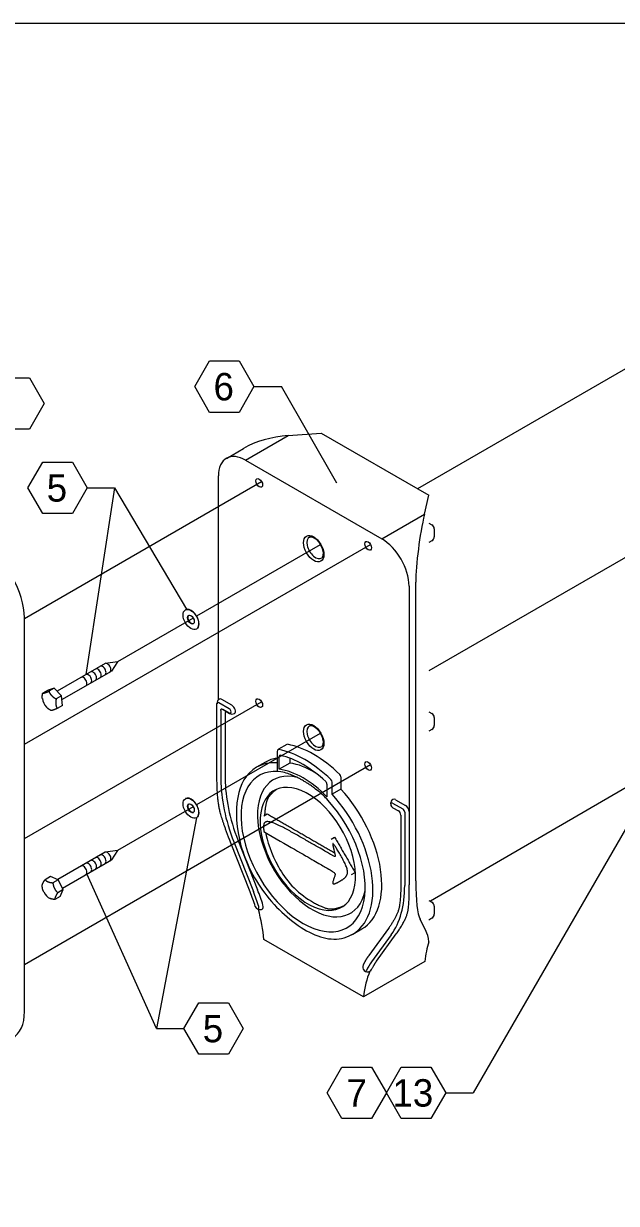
# Model space of a CAD drawing. Extents: x 99862 to 103151, y 100000 to 105076.
# Drawn here: x 100459 to 100805, y 104386 to 105076 of the extents above; entities that cross this region are included whole.
import ezdxf

# ---------------------------------------------------------------- set-up
doc = ezdxf.new("R2010")
doc.units = 0
for name, color, linetype in [('Level 1', 7, 'Continuous'), ('Level 15', 7, 'Continuous'), ('Level 16', 7, 'Continuous'), ('Level 20', 7, 'Continuous'), ('Level 33', 7, 'Continuous'), ('Level 34', 7, 'Continuous'), ('Level 35', 7, 'Continuous'), ('Level 36', 7, 'Continuous'), ('Level 38', 7, 'Continuous'), ('Level 41', 7, 'Continuous')]:
    doc.layers.add(name, color=color, linetype=linetype)

msp = doc.modelspace()

# ---------------------------------------------------------------- linework, layer by layer
at = {"layer": 'Level 1'}
msp.add_lwpolyline([(99862, 102999.5), (103151, 102999.5), (103151, 105075.5), (99862, 105075.5)], close=True, dxfattribs=at)
at = {"layer": 'Level 15'}
for p, q in [((100593.66, 104863.43), (100609.66, 104863.43)), ((100642.16, 104807.13), (100609.66, 104863.43)), ((100512.23, 104804.29), (100495.5, 104695.25)), ((100496.23, 104804.29), (100512.23, 104804.29)), ((100512.23, 104804.29), (100554.29, 104733.38)), ((100822.1, 104624.87), (100721.67, 104450.91)), ((100560.04, 104611.6), (100536.75, 104488.47)), ((100536.75, 104488.47), (100496.05, 104578.84)), ((100536.75, 104488.47), (100552.75, 104488.47)), ((100705.67, 104450.91), (100721.67, 104450.91))]:
    msp.add_line(p, q, dxfattribs=at)
at = {"layer": 'Level 16'}
for p, q in [((100824.93, 104882.2), (100689.17, 104803.82)), ((100459.6, 104728.01), (100598.14, 104808)), ((100459.6, 104654.53), (100661.78, 104771.26)), ((100632.42, 104771.05), (100560.18, 104729.35)), ((100824.93, 104771.97), (100695.86, 104697.45)), ((100558.23, 104728.22), (100514.01, 104702.69)), ((100459.6, 104599.42), (100598.14, 104679.4)), ((100632.42, 104660.82), (100560.18, 104619.12)), ((100459.6, 104525.93), (100661.78, 104642.66)), ((100828.58, 104639.5), (100696.72, 104562.84)), ((100558.23, 104617.99), (100514.01, 104592.46))]:
    msp.add_line(p, q, dxfattribs=at)
at = {"layer": 'Level 20'}
for points in [[(100559.03, 104863.43), (100567.69, 104878.42), (100585.01, 104878.42), (100593.66, 104863.43), (100585.01, 104848.43), (100567.69, 104848.43), (100559.03, 104863.43)], [(100436.51, 104853.56), (100445.17, 104868.56), (100462.49, 104868.56), (100471.13, 104853.56), (100462.49, 104838.57), (100445.17, 104838.57), (100436.51, 104853.56)], [(100461.6, 104804.29), (100470.26, 104819.29), (100487.58, 104819.29), (100496.23, 104804.29), (100487.58, 104789.29), (100470.26, 104789.29), (100461.6, 104804.29)], [(100552.75, 104488.47), (100561.41, 104503.47), (100578.73, 104503.47), (100587.38, 104488.47), (100578.73, 104473.48), (100561.41, 104473.48), (100552.75, 104488.47)], [(100636.42, 104450.91), (100645.08, 104465.91), (100662.4, 104465.91), (100671.04, 104450.91), (100662.4, 104435.92), (100645.08, 104435.92), (100636.42, 104450.91)], [(100671.04, 104450.91), (100679.7, 104465.91), (100697.03, 104465.91), (100705.67, 104450.91), (100697.03, 104435.92), (100679.7, 104435.92), (100671.04, 104450.91)]]:
    msp.add_lwpolyline(points, dxfattribs=at)
at = {"layer": 'Level 33'}
for p, q in [((100588.78, 104820.45), (100613.69, 104834.83)), ((100613.69, 104834.83), (100632.85, 104836.34)), ((100632.85, 104836.34), (100695.86, 104799.96)), ((100577.53, 104821.56), (100587.64, 104827.4)), ((100588.78, 104820.45), (100668.33, 104774.52)), ((100572.87, 104680.43), (100572.87, 104811.26)), ((100693.24, 104788.9), (100695.86, 104799.96)), ((100668.33, 104774.52), (100693.24, 104788.9)), ((100695.86, 104783.79), (100697.58, 104782.8)), ((100698.99, 104780.36), (100698.99, 104775.77)), ((100697.58, 104773.33), (100695.86, 104772.34)), ((100684.24, 104746.96), (100684.24, 104615.3)), ((100688.22, 104574.73), (100688.22, 104749.26)), ((100572.05, 104635.59), (100572.05, 104678.45)), ((100579.18, 104675.33), (100573.21, 104678.77)), ((100574.32, 104674.3), (100574.32, 104633.99)), ((100580.83, 104677.3), (100574.86, 104680.74)), ((100579.18, 104672.77), (100575.42, 104674.94)), ((100576.27, 104674.39), (100579.42, 104672.57)), ((100576.85, 104672.7), (100576.85, 104634.44)), ((100695.86, 104673.57), (100697.58, 104672.57)), ((100698.99, 104670.14), (100698.99, 104665.54)), ((100626.11, 104665.3), (100626.04, 104665.26)), ((100697.58, 104663.11), (100695.86, 104662.11)), ((100612.94, 104654.45), (100608.02, 104651.61)), ((100607.3, 104650.18), (100607.3, 104638.91)), ((100608.43, 104639.95), (100608.43, 104647.4)), ((100614.64, 104646.41), (100614.64, 104643.53)), ((100633.07, 104653.08), (100633.07, 104653.08)), ((100600.43, 104644.11), (100595.23, 104641.11)), ((100614.64, 104643.53), (100608.43, 104639.95)), ((100644.47, 104635.44), (100644.47, 104628.31)), ((100636.27, 104631.33), (100636.27, 104623.87)), ((100639.27, 104625.31), (100639.26, 104632.43)), ((100644.47, 104628.31), (100639.27, 104625.31)), ((100674.63, 104620.21), (100680.6, 104616.77)), ((100676.29, 104622.18), (100682.25, 104618.74)), ((100674.88, 104617.45), (100678.03, 104615.63)), ((100679.44, 104613.2), (100679.44, 104573.58)), ((100681.71, 104614.85), (100681.71, 104571.99)), ((100684.24, 104615.3), (100684.24, 104572.44)), ((100584.3, 104598.63), (100595.78, 104569.54)), ((100591.46, 104568.31), (100579.98, 104597.4)), ((100581.89, 104597.6), (100593.37, 104568.51)), ((100695.86, 104563.34), (100697.58, 104562.34)), ((100698.99, 104559.91), (100698.99, 104555.32)), ((100694.28, 104545.27), (100690.66, 104552.39)), ((100697.58, 104552.88), (100695.86, 104551.88)), ((100651.48, 104543.68), (100656.68, 104546.69)), ((100672.25, 104547.02), (100660.77, 104531.18)), ((100673.83, 104543.22), (100662.35, 104527.38)), ((100665.33, 104527.88), (100676.81, 104543.72)), ((100657.64, 104506.97), (100599.47, 104540.56)), ((100693.44, 104527.64), (100657.64, 104506.97))]:
    msp.add_line(p, q, dxfattribs=at)
for centre, radius, start, end in [((100696.17, 104780.36), 2.81, 0, 60), ((100696.17, 104775.77), 2.81, 300, 0), ((100574.86, 104678.45), 2.81, 120, 180), ((100580.83, 104675), 2.81, 240, 300), ((100696.17, 104670.14), 2.81, 0, 60), ((100696.17, 104665.54), 2.81, 300, 0), ((100676.29, 104619.89), 2.81, 120, 240), ((100676.63, 104613.2), 2.81, 360, 60), ((100597.1, 104560.71), 2.79, 197.75646, 251.96196), ((100597.1, 104560.71), 2.79, 251.96196, 300.46555), ((100696.17, 104559.91), 2.81, 0, 60), ((100696.17, 104555.32), 2.81, 300, 0), ((100660.01, 104524.42), 2.81, 154.08148, 299.62181), ((100660.01, 104524.42), 2.81, 299.62181, 328.21805)]:
    msp.add_arc(centre, radius, start, end, dxfattribs=at)
for centre, major_axis, ratio, start_param, end_param in [((100613.69, 104816.46), (36.79, 3.84), 0.494566, 1.519169, 2.304567), ((100588.78, 104802.07), (-11.25, 19.49), 0.57735, 6.267379, 7.068583), ((100588.78, 104802.07), (-11.25, 19.49), 0.57735, 5.497787, 6.26552), ((100693.24, 104770.53), (3.85, 28.1), 0.114691, 0.874148, 2.444944), ((100629.55, 104769.4), (-3.52, 6.09), 0.57735, 6.244605, 9.508637), ((100668.33, 104756.15), (11.25, -19.49), 0.57735, 0.785398, 2.356194), ((100574.86, 104678.45), (-1.41, 2.44), 0.57735, 5.497787, 6.283185), ((100573.21, 104677.49), (0.78, -1.36), 0.57735, 2.356194, 3.926991), ((100574.86, 104678.45), (4.13, -4.48), 0.368973, 5.220152, 5.415219), ((100579.18, 104674.05), (0.78, -1.36), 0.57735, 5.497787, 8.63938), ((100580.83, 104675), (-1.41, 2.44), 0.57735, 3.141593, 5.497787), ((100578.84, 104671.56), (-1.41, 2.44), 0.57735, 0.159548, 0.785398), ((100629.55, 104659.17), (-3.52, 6.09), 0.57735, 6.244605, 9.508637), ((100613.64, 104653.23), (-0.7, 1.22), 0.57735, 5.822618, 6.283185), ((100628.56, 104593.48), (-33.75, 58.46), 0.57735, 5.172956, 5.822618), ((100628.56, 104595.4), (-28.13, 48.71), 0.57735, 6.069803, 6.28319), ((100608.34, 104650.34), (0.26, 1.38), 0.731418, 0.561152, 1.823018), ((100623.35, 104590.47), (33.75, -58.46), 0.57735, 2.031363, 2.681026), ((100609.43, 104646.83), (0.7, -1.22), 0.57735, 2.649261, 3.926991), ((100622.35, 104589.9), (32.34, -56.02), 0.57735, 2.063128, 2.649261), ((100622.37, 104591.82), (25.65, -44.43), 0.57735, 2.770312, 8.225262), ((100623.36, 104592.4), (28.13, -48.71), 0.57735, 2.771884, 3.141593), ((100622.35, 104589.9), (27.55, -47.71), 0.57735, 1.990752, 2.721637), ((100628.56, 104593.48), (-27.55, 47.71), 0.57735, 5.467511, 5.86323), ((100628.89, 104602.48), (-38.59, 66.84), 0.57735, 0.785398, 1.318407), ((100630.55, 104603.44), (37.97, -65.76), 0.57735, 3.926991, 4.46), ((100607.45, 104638.82), (0.107, -0.186), 0.57735, 3.926991, 5.90159), ((100635.28, 104631.9), (0.7, -1.22), 0.57735, 0.785398, 2.063128), ((100638.26, 104633), (-0.7, 1.22), 0.57735, 3.926991, 5.172956), ((100643.47, 104636.01), (-0.7, 1.22), 0.57735, 3.926991, 5.172956), ((100628.56, 104595.4), (-28.13, 48.71), 0.57735, 3.141593, 5.08627), ((100623.36, 104592.4), (28.13, -48.71), 0.57735, 6.254516, 8.227863), ((100674.63, 104618.93), (0.78, -1.36), 0.57735, 2.356194, 5.497787), ((100676.29, 104619.89), (-1.41, 2.44), 0.57735, 5.497787, 6.283185), ((100680.6, 104615.49), (0.78, -1.36), 0.57735, 0.785398, 2.356194), ((100682.25, 104616.44), (-1.41, 2.44), 0.57735, 3.926991, 5.497787), ((100624.92, 104604.78), (40.16, -69.56), 0.57735, 0.252389, 0.785398), ((100705.8, 104649.18), (-13.48, -98.36), 0.114691, 5.586537, 6.119546), ((100594.06, 104569.36), (2.62, 1.03), 0.203894, 3.101194, 3.181991), ((100544.45, 104563.42), (-38.59, 66.84), 0.57735, 4.339992, 4.46), ((100544.45, 104563.42), (40.16, -69.56), 0.57735, 1.198399, 1.318408), ((100546.1, 104564.38), (-40.78, 70.64), 0.57735, 4.339992, 4.46), ((100595.46, 104559.78), (0.78, -1.36), 0.57735, 4.712389, 7.481585), ((100544.12, 104565.53), (-39.38, 68.2), 0.57735, 4.035936, 4.286649), ((100597.11, 104560.74), (-1.41, 2.44), 0.57735, 3.141594, 4.339992), ((100679.14, 104448.47), (-13.48, -98.36), 0.114691, 2.760167, 2.977954), ((100748.8, 104488.69), (-39.38, 68.2), 0.57735, 0.470176, 0.676453), ((100658.36, 104523.47), (0.78, -1.36), 0.57735, 4.712389, 6.655582), ((100709.36, 104468.22), (-38.59, 66.84), 0.57735, 0.252389, 0.372397), ((100713, 104468.02), (-39.38, 68.2), 0.57735, 0.400156, 0.676453)]:
    msp.add_ellipse(centre, major_axis=major_axis, ratio=ratio, start_param=start_param, end_param=end_param, dxfattribs=at)
for centre, major_axis in [((100596.74, 104807.19), (-1.41, 2.44)), ((100628.56, 104768.82), (-4.22, 7.31)), ((100660.38, 104770.45), (-1.41, 2.44)), ((100596.74, 104678.59), (-1.41, 2.44)), ((100628.56, 104658.6), (-4.22, 7.31)), ((100660.38, 104641.85), (-1.41, 2.44))]:
    msp.add_ellipse(centre, major_axis=major_axis, ratio=0.57735, dxfattribs=at)
for points, degree in [([(100626.17, 104775.56), (100626.71, 104775.8), (100627.66, 104775.76), (100628.85, 104775.07)], 2), ([(100628.85, 104775.07), (100631.41, 104773.63), (100634.95, 104767.1), (100633.8, 104763.93), (100633.35, 104763.5)], 3), ([(100574.32, 104674.3), (100574.32, 104674.44), (100574.32, 104674.57), (100574.35, 104674.7), (100574.37, 104674.82), (100574.41, 104674.94), (100574.47, 104675.03), (100574.51, 104675.08), (100574.57, 104675.12), (100574.63, 104675.15), (100574.69, 104675.17), (100574.77, 104675.17), (100574.84, 104675.16), (100574.97, 104675.15), (100575.1, 104675.1), (100575.24, 104675.03), (100575.3, 104675), (100575.36, 104674.97), (100575.42, 104674.94)], 3), ([(100626.17, 104665.33), (100626.71, 104665.57), (100627.66, 104665.53), (100628.85, 104664.84)], 2), ([(100628.85, 104664.84), (100631.41, 104663.4), (100634.95, 104656.88), (100633.8, 104653.7), (100633.35, 104653.27)], 3), ([(100595.23, 104641.11), (100588.75, 104637.08), (100582.31, 104625.58), (100583.73, 104595.37), (100599.32, 104564.71), (100626.45, 104541.48), (100642.96, 104539.14), (100650.86, 104543.34)], 3), ([(100579.97, 104597.42), (100574.81, 104610.47), (100572.04, 104623.76), (100572.05, 104635.59)], 2), ([(100636.96, 104621.75), (100634.66, 104624.19), (100632.26, 104626.41), (100628.6, 104629.27), (100627.38, 104630.14), (100624.96, 104631.73), (100623.76, 104632.47), (100621.26, 104633.91), (100619.96, 104634.62), (100617.42, 104635.89), (100616.17, 104636.45), (100612.49, 104637.83), (100610.08, 104638.39), (100607.77, 104638.61)], 3), ([(100679.44, 104573.58), (100679.46, 104562.62), (100676.86, 104553.34), (100672.25, 104547.02)], 2), ([(100676.81, 104543.72), (100682.25, 104551.57), (100684.59, 104561.2), (100684.24, 104572.44)], 2), ([(100660.77, 104531.18), (100659.54, 104529.48), (100658.44, 104527.63), (100657.48, 104525.65)], 2), ([(100662.4, 104522.94), (100663.9, 104525.77), (100664.59, 104526.86), (100665.33, 104527.88)], 2)]:
    msp.add_open_spline(points, degree=degree, dxfattribs=at)
at = {"layer": 'Level 34'}
for centre, major_axis, start_param, end_param in [((100627.54, 104594.81), (22.5, -38.97), 2.632698, 6.851151), ((100625.15, 104593.43), (19.69, -34.1), 2.394599, 8.675608)]:
    msp.add_ellipse(centre, major_axis=major_axis, ratio=0.57735, start_param=start_param, end_param=end_param, dxfattribs=at)
at = {"layer": 'Level 35'}
for p, q in [((100599.47, 104612.7), (100601.46, 104613.84)), ((100638.8, 104599.18), (100640.78, 104600.33)), ((100650.73, 104578.51), (100652.72, 104579.66))]:
    msp.add_line(p, q, dxfattribs=at)
for points, degree in [([(100601.46, 104613.84), (100621.12, 104602.49), (100640.78, 104591.14)], 2), ([(100599.47, 104603.51), (100598.85, 104608.46), (100599.47, 104612.7), (100619.77, 104600.98), (100640.07, 104589.26), (100641.45, 104588.46), (100641.01, 104590.22), (100639.9, 104594.7), (100638.8, 104599.18), (100644.76, 104588.84), (100650.73, 104578.51), (100644.76, 104575.06), (100638.8, 104571.62), (100639.9, 104574.82), (100641.01, 104578.02), (100641.45, 104579.27), (100640.07, 104580.07), (100619.77, 104591.79), (100599.47, 104603.51)], 4), ([(100640.78, 104600.33), (100646.75, 104589.99), (100652.72, 104579.66)], 2)]:
    msp.add_open_spline(points, degree=degree, dxfattribs=at)
at = {"layer": 'Level 36'}
for points, degree in [([(100606.9, 104628.25), (100602.75, 104625.13), (100600.32, 104619.6), (100599.83, 104612.9)], 2), ([(100600.42, 104602.96), (100601.19, 104598.64), (100606.21, 104582.49), (100618.27, 104568.02), (100627.26, 104562.84)], 3), ([(100627.26, 104562.84), (100633.95, 104558.93), (100640.81, 104557.9), (100646.15, 104560.2)], 2)]:
    msp.add_open_spline(points, degree=degree, dxfattribs=at)
at = {"layer": 'Level 38'}
for p, q in [((100506.66, 104701.7), (100478.71, 104685.55)), ((100514.01, 104702.69), (100506.95, 104701.8)), ((100514.01, 104702.69), (100510.37, 104697.34)), ((100481.52, 104680.68), (100510.37, 104697.34)), ((100473.4, 104686.14), (100470.24, 104684.32)), ((100477.02, 104687.32), (100473.4, 104686.14)), ((100477.02, 104687.32), (100473.86, 104685.5)), ((100481.27, 104682.87), (100477.02, 104687.32)), ((100481.27, 104682.87), (100478.12, 104681.05)), ((100481.91, 104677.25), (100481.27, 104682.87)), ((100481.91, 104677.25), (100478.76, 104675.43)), ((100506.66, 104591.47), (100479.08, 104575.54)), ((100514.01, 104592.46), (100507, 104591.59)), ((100514.01, 104592.46), (100510.37, 104587.11)), ((100481.73, 104570.58), (100510.37, 104587.11)), ((100474.79, 104577.27), (100471.64, 104575.45)), ((100479.34, 104575.43), (100474.79, 104577.27)), ((100479.34, 104575.43), (100476.19, 104573.62)), ((100482.2, 104569.63), (100479.34, 104575.43)), ((100480.51, 104565.67), (100477.36, 104563.85)), ((100482.2, 104569.63), (100479.04, 104567.81)), ((100480.51, 104565.67), (100482.2, 104569.63))]:
    msp.add_line(p, q, dxfattribs=at)
for centre, major_axis in [((100556.82, 104727.41), (-3.22, 5.58)), ((100556.82, 104727.41), (1.41, -2.44)), ((100556.82, 104617.18), (-3.22, 5.58)), ((100556.82, 104617.18), (1.41, -2.44))]:
    msp.add_ellipse(centre, major_axis=major_axis, ratio=0.57735, dxfattribs=at)
for centre, major_axis, start_param, end_param in [((100556.96, 104727.49), (-3.22, 5.58), 3.119941, 6.283185), ((100556.96, 104727.49), (1.41, -2.44), 3.19121, 6.233568), ((100473.99, 104679.58), (2.81, -4.87), 4.066603, 5.113801), ((100556.96, 104617.26), (-3.22, 5.58), 4.16506, 6.304836), ((100556.96, 104617.26), (1.41, -2.44), 3.19121, 6.233568), ((100556.96, 104617.26), (-3.22, 5.58), 3.119941, 4.16506), ((100473.99, 104569.36), (2.81, -4.87), 4.59906, 5.646257)]:
    msp.add_ellipse(centre, major_axis=major_axis, ratio=0.57735, start_param=start_param, end_param=end_param, dxfattribs=at)
for points in [[(100470.05, 104681.22), (100469.94, 104682.18), (100470.04, 104683.25), (100470.24, 104684.32)], [(100470.24, 104684.32), (100470.52, 104684.34), (100470.92, 104684.41), (100471.54, 104684.62)], [(100471.54, 104684.62), (100472.16, 104684.82), (100472.98, 104685.14), (100473.86, 104685.5)], [(100473.86, 104685.5), (100474.24, 104684.62), (100474.75, 104683.74), (100475.48, 104682.98)], [(100475.48, 104682.98), (100476.21, 104682.22), (100477.13, 104681.59), (100478.12, 104681.05)], [(100478.12, 104681.05), (100477.92, 104679.98), (100477.82, 104678.91), (100477.93, 104677.95)], [(100475.14, 104674.26), (100474.16, 104674.79), (100473.23, 104675.42), (100472.5, 104676.19)], [(100476.44, 104674.55), (100475.82, 104674.35), (100475.41, 104674.27), (100475.14, 104674.26)], [(100478.76, 104675.43), (100477.88, 104675.07), (100477.06, 104674.75), (100476.44, 104674.55)], [(100477.93, 104677.95), (100478.04, 104676.98), (100478.35, 104676.16), (100478.76, 104675.43)], [(100469.96, 104571.49), (100469.92, 104571.95), (100470, 104572.5), (100470.29, 104573.18)], [(100470.88, 104568.29), (100470.39, 104569.29), (100470.11, 104570.39), (100469.96, 104571.49)], [(100470.29, 104573.18), (100470.58, 104573.86), (100471.07, 104574.64), (100471.64, 104575.45)], [(100471.64, 104575.45), (100472.06, 104574.98), (100472.62, 104574.55), (100473.4, 104574.24)], [(100473.4, 104574.24), (100474.18, 104573.92), (100475.15, 104573.73), (100476.19, 104573.62)], [(100476.19, 104573.62), (100476.34, 104572.51), (100476.61, 104571.41), (100477.1, 104570.42)], [(100477.36, 104563.85), (100476.33, 104563.97), (100475.36, 104564.16), (100474.58, 104564.47)], [(100477.1, 104570.42), (100477.59, 104569.42), (100478.28, 104568.57), (100479.04, 104567.81)], [(100477.69, 104565.54), (100477.4, 104564.86), (100477.33, 104564.31), (100477.36, 104563.85)], [(100479.04, 104567.81), (100478.47, 104567.01), (100477.98, 104566.22), (100477.69, 104565.54)]]:
    msp.add_open_spline(points, degree=2, dxfattribs=at)
at = {"layer": 'Level 41'}
msp.add_line((100459.6, 104498.37), (100459.6, 104728.38), dxfattribs=at)
for centre, major_axis, start_param, end_param in [((100435.73, 104742.16), (-16.88, 29.23), 3.926991, 5.497787), ((100508.07, 104699.26), (1.41, -2.44), 6.28318, 9.424778), ((100496.91, 104692.82), (1.41, -2.44), 6.28318, 9.424778), ((100499.7, 104694.43), (1.41, -2.44), 6.28318, 9.424778), ((100502.49, 104696.04), (1.41, -2.44), 6.28318, 9.424778), ((100505.28, 104697.65), (1.41, -2.44), 6.28318, 9.424778), ((100494.12, 104691.2), (1.41, -2.44), 6.28318, 9.424778), ((100508.07, 104589.03), (1.41, -2.44), 6.28318, 9.424778), ((100496.91, 104582.59), (1.41, -2.44), 6.28318, 9.424778), ((100499.7, 104584.2), (1.41, -2.44), 6.28318, 9.424778), ((100502.49, 104585.81), (1.41, -2.44), 6.28318, 9.424778), ((100505.28, 104587.42), (1.41, -2.44), 6.28318, 9.424778), ((100494.12, 104580.98), (1.41, -2.44), 6.28318, 9.424778), ((100435.73, 104512.15), (16.88, -29.23), 0, 0.785398)]:
    msp.add_ellipse(centre, major_axis=major_axis, ratio=0.57735, start_param=start_param, end_param=end_param, dxfattribs=at)

# ---------------------------------------------------------------- texts
at = {"layer": 'Level 20'}
for s, p in [('6', (100570.04, 104855.43)), ('5', (100472.61, 104796.29)), ('5', (100563.76, 104480.47)), ('7', (100647.79, 104442.92)), ('13', (100674.58, 104442.91))]:
    msp.add_text(s, height=16, dxfattribs=at).set_placement(p)

doc.saveas('drawing.dxf')
